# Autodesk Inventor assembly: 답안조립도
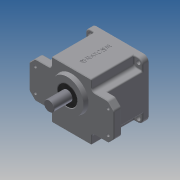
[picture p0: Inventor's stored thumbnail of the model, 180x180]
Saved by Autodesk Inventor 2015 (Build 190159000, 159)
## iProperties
Created: 2016-02
Part Number: 답안조립도
Document SubType Name: Assembly
Designer: Administrator
Author: Administrator
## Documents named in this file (10)
- C:\Users\Administrator\Desktop\460209V1007\답안조립도.iam
- C:\Users\Administrator\Desktop\460209V1007\본체.ipt
- C:\Users\Administrator\Desktop\460209V1007\베어링 608.ipt
- C:\Users\Administrator\Desktop\460209V1007\오일실 8 22 7.ipt
- C:\Users\Administrator\Desktop\460209V1007\커버.ipt
- C:\Users\Administrator\Desktop\460209V1007\볼트 M4 x 10.ipt
- C:\Users\Administrator\Desktop\460209V1007\베어링 6003.ipt
- C:\Users\Administrator\Desktop\460209V1007\오일실 17 32 8.ipt
- C:\Users\Administrator\Desktop\460209V1007\메인축.ipt
- C:\Users\Administrator\Desktop\460209V1007\서브축.ipt
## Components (2 placed, 1 different names)
1. ISO 4762 M4 x 10:1 — Insert:1
2. ISO 4762 M4 x 10:2 — Insert:2
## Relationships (2: Insert 2)
- Insert:1: ISO 4762 M4 x 10:1
- Insert:2: ISO 4762 M4 x 10:2
